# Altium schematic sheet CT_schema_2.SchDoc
size 289 x 159 mm
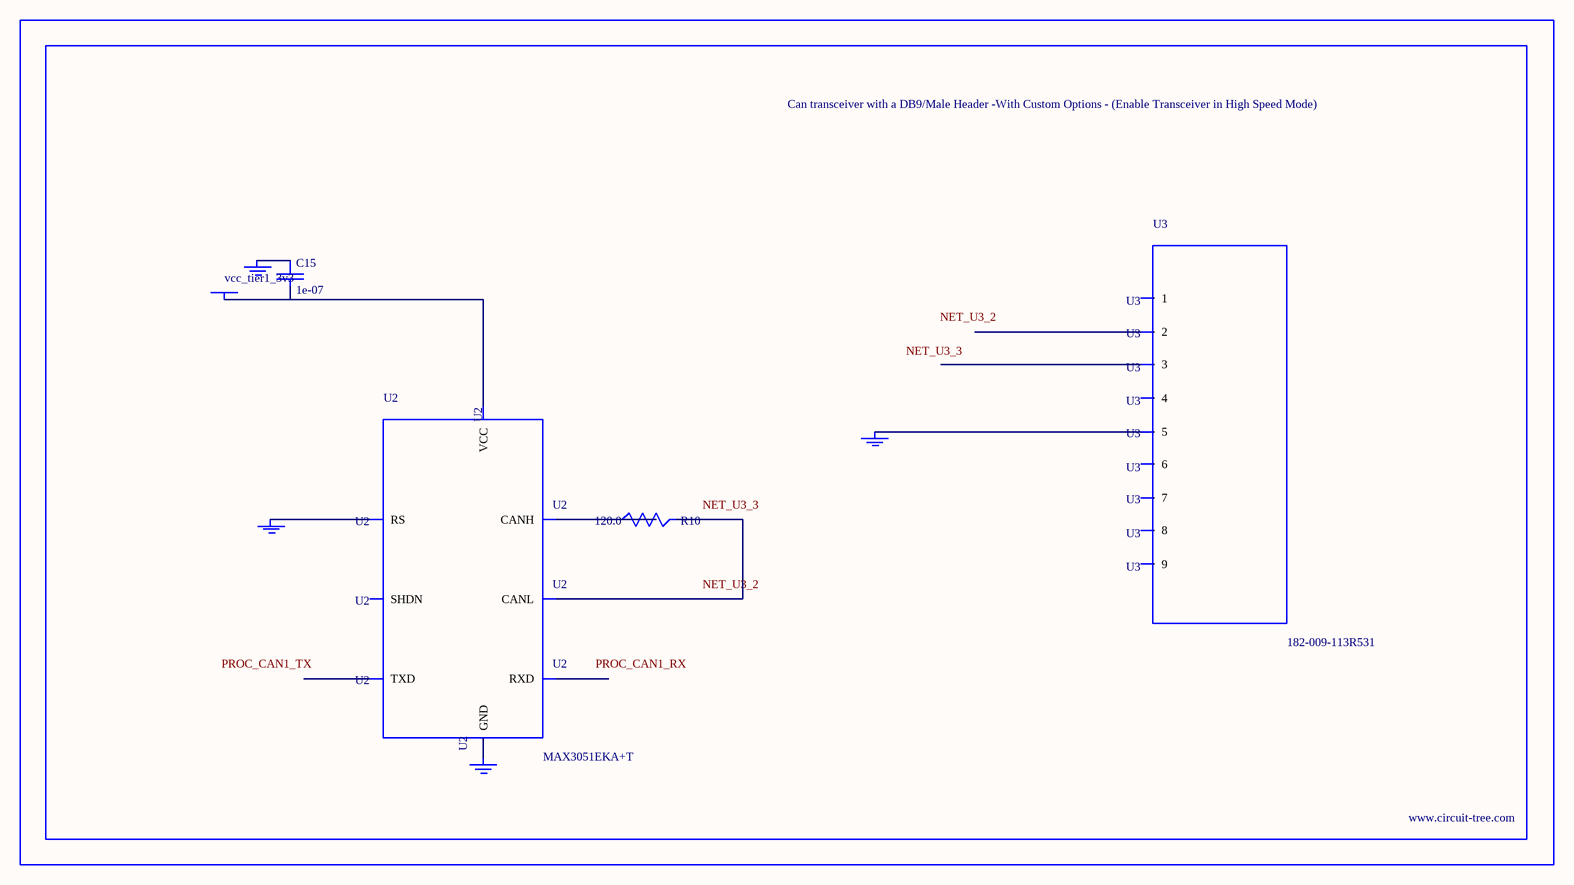
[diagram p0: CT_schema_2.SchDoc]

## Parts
BORDER1  (no value)
C15  1e-07  [C0402]
GND_INSTANCE_1_0  (no value)
GND_INSTANCE_1_1  (no value)
GND_INSTANCE_1_2  (no value)
GND_INSTANCE_1_3  (no value)
POWER_INSTANCE_1_0  vcc_tier1_3v3
R10  120.0  [R0603]
U2  MAX3051EKA+T  [SOT-23-8]
U3  182-009-113R531  [182-009-MALE]

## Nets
NetC15_1: C15.1 GND_INSTANCE_1_0.0(GND)
NetC15_2: C15.2 POWER_INSTANCE_1_0.0(PWR) U2.3(VCC)
NetGND_INSTANCE_1_1_0: GND_INSTANCE_1_1.0(GND) U2.8(RS)
NetGND_INSTANCE_1_2_0: GND_INSTANCE_1_2.0(GND) U2.2(GND)
NetGND_INSTANCE_1_3_0: GND_INSTANCE_1_3.0(GND) U3.5
NetR10_1: R10.1 U2.7(CANH)
NetR10_2: R10.2 U2.6(CANL)

Not connected (* = marked no-connect by the designer): U2 1(TXD) 4(RXD) 5(SHDN); U3 1 2 3 4 6 7 8 9

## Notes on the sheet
- Labels drawn without touching a wire or pin: NET_U3_2, NET_U3_3, PROC_CAN1_RX, PROC_CAN1_TX

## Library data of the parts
BORDER1 = BORDER_PAGE1
C15 = C0402C104K3RACTU
GND_INSTANCE_1_0-GND_INSTANCE_1_3 = GND
POWER_INSTANCE_1_0 = PWR
R10 = RC0603JR-07120RL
